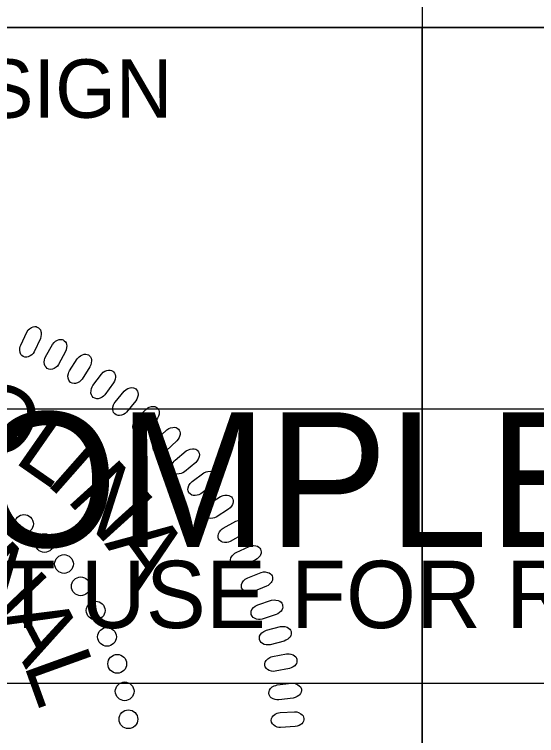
# Model space of a CAD drawing. Extents: x 505602 to 507286, y 483109 to 484209.
# Drawn here: x 507134.2 to 507178.9, y 484098.1 to 484159.8 of the extents above; entities that cross this region are included whole.
import ezdxf

# ---------------------------------------------------------------- set-up
doc = ezdxf.new("R2010")
doc.units = 0
for name, color, linetype in [('Sheet Layout Profile Border Port 2', 7, 'Continuous'), ('Sheet PE Seal Cell', 7, 'Continuous'), ('Sheet Profile CELL', 7, 'Continuous'), ('Sheet Sticker Incomplete CELL', 7, 'Continuous')]:
    doc.layers.add(name, color=color, linetype=linetype)

msp = doc.modelspace()

# ---------------------------------------------------------------- linework, layer by layer
at = {"layer": 'Sheet Layout Profile Border Port 2'}
msp.add_lwpolyline([(506769.08, 484183.712), (507169.08, 484183.712), (507169.08, 483683.712), (506769.08, 483683.712)], close=True, dxfattribs=at)
at = {"layer": 'Sheet PE Seal Cell'}
for points in [[(507134.756, 484131.474), (507135.278, 484132.584), (507135.405, 484132.766), (507135.512, 484132.87), (507135.686, 484132.976), (507135.821, 484133.034), (507135.956, 484133.058), (507136.068, 484133.05), (507136.178, 484133.02), (507136.27, 484132.954), (507136.366, 484132.876), (507136.435, 484132.778), (507136.487, 484132.642), (507136.508, 484132.545), (507136.505, 484132.381), (507136.482, 484132.193), (507136.435, 484132.039), (507135.906, 484130.899), (507135.814, 484130.755), (507135.713, 484130.648), (507135.564, 484130.542), (507135.403, 484130.463), (507135.281, 484130.432), (507135.114, 484130.445), (507134.97, 484130.491), (507134.852, 484130.591), (507134.779, 484130.68), (507134.706, 484130.825), (507134.67, 484131.029), (507134.686, 484131.22), (507134.714, 484131.35)], [(507136.88, 484130.459), (507137.471, 484131.534), (507137.609, 484131.707), (507137.722, 484131.805), (507137.902, 484131.899), (507138.04, 484131.949), (507138.177, 484131.964), (507138.288, 484131.949), (507138.396, 484131.912), (507138.485, 484131.841), (507138.575, 484131.757), (507138.638, 484131.654), (507138.682, 484131.516), (507138.695, 484131.418), (507138.683, 484131.254), (507138.648, 484131.068), (507138.591, 484130.917), (507137.992, 484129.813), (507137.89, 484129.675), (507137.784, 484129.574), (507137.629, 484129.478), (507137.462, 484129.409), (507137.339, 484129.386), (507137.173, 484129.41), (507137.032, 484129.464), (507136.92, 484129.571), (507136.852, 484129.666), (507136.789, 484129.814), (507136.766, 484130.02), (507136.794, 484130.21), (507136.83, 484130.338)], [(507138.938, 484129.274), (507139.595, 484130.309), (507139.744, 484130.475), (507139.863, 484130.564), (507140.049, 484130.647), (507140.19, 484130.688), (507140.327, 484130.695), (507140.437, 484130.673), (507140.543, 484130.629), (507140.626, 484130.553), (507140.711, 484130.463), (507140.768, 484130.357), (507140.802, 484130.216), (507140.81, 484130.117), (507140.787, 484129.954), (507140.741, 484129.771), (507140.674, 484129.624), (507140.007, 484128.559), (507139.897, 484128.428), (507139.784, 484128.335), (507139.623, 484128.248), (507139.454, 484128.19), (507139.329, 484128.174), (507139.164, 484128.208), (507139.027, 484128.272), (507138.923, 484128.385), (507138.861, 484128.484), (507138.807, 484128.636), (507138.797, 484128.843), (507138.837, 484129.031), (507138.881, 484129.156)], [(507140.938, 484128.001), (507141.659, 484128.993), (507141.818, 484129.149), (507141.943, 484129.231), (507142.133, 484129.302), (507142.276, 484129.333), (507142.413, 484129.332), (507142.522, 484129.302), (507142.625, 484129.253), (507142.703, 484129.171), (507142.782, 484129.077), (507142.832, 484128.967), (507142.858, 484128.824), (507142.86, 484128.724), (507142.826, 484128.564), (507142.769, 484128.384), (507142.693, 484128.241), (507141.96, 484127.221), (507141.842, 484127.097), (507141.723, 484127.01), (507141.558, 484126.934), (507141.384, 484126.886), (507141.259, 484126.879), (507141.097, 484126.923), (507140.964, 484126.995), (507140.866, 484127.115), (507140.811, 484127.217), (507140.767, 484127.372), (507140.77, 484127.58), (507140.821, 484127.765), (507140.873, 484127.887)], [(507142.832, 484126.584), (507143.614, 484127.529), (507143.783, 484127.674), (507143.912, 484127.749), (507144.107, 484127.808), (507144.251, 484127.831), (507144.389, 484127.82), (507144.495, 484127.785), (507144.594, 484127.728), (507144.668, 484127.642), (507144.741, 484127.542), (507144.783, 484127.429), (507144.8, 484127.286), (507144.796, 484127.186), (507144.751, 484127.028), (507144.683, 484126.852), (507144.599, 484126.714), (507143.804, 484125.742), (507143.678, 484125.625), (507143.554, 484125.546), (507143.384, 484125.481), (507143.208, 484125.444), (507143.082, 484125.445), (507142.923, 484125.499), (507142.795, 484125.579), (507142.705, 484125.705), (507142.657, 484125.81), (507142.623, 484125.968), (507142.639, 484126.174), (507142.701, 484126.356), (507142.761, 484126.475)], [(507144.603, 484125.07), (507145.444, 484125.964), (507145.621, 484126.099), (507145.755, 484126.165), (507145.953, 484126.212), (507146.099, 484126.225), (507146.235, 484126.206), (507146.339, 484126.164), (507146.434, 484126.101), (507146.502, 484126.01), (507146.569, 484125.906), (507146.604, 484125.791), (507146.612, 484125.647), (507146.601, 484125.547), (507146.547, 484125.392), (507146.468, 484125.221), (507146.376, 484125.089), (507145.52, 484124.168), (507145.388, 484124.06), (507145.259, 484123.989), (507145.085, 484123.935), (507144.908, 484123.909), (507144.782, 484123.918), (507144.626, 484123.982), (507144.504, 484124.069), (507144.423, 484124.201), (507144.381, 484124.309), (507144.356, 484124.468), (507144.385, 484124.674), (507144.459, 484124.851), (507144.526, 484124.966)], [(507146.348, 484123.377), (507147.243, 484124.216), (507147.428, 484124.339), (507147.566, 484124.397), (507147.766, 484124.431), (507147.912, 484124.435), (507148.047, 484124.408), (507148.148, 484124.359), (507148.24, 484124.291), (507148.302, 484124.195), (507148.362, 484124.088), (507148.39, 484123.971), (507148.389, 484123.826), (507148.371, 484123.728), (507148.308, 484123.576), (507148.219, 484123.41), (507148.117, 484123.284), (507147.206, 484122.419), (507147.067, 484122.319), (507146.935, 484122.256), (507146.757, 484122.213), (507146.578, 484122.199), (507146.453, 484122.215), (507146.302, 484122.289), (507146.185, 484122.384), (507146.112, 484122.52), (507146.077, 484122.631), (507146.063, 484122.792), (507146.105, 484122.995), (507146.19, 484123.167), (507146.264, 484123.277)], [(507147.96, 484121.631), (507148.905, 484122.412), (507149.099, 484122.523), (507149.24, 484122.572), (507149.441, 484122.594), (507149.588, 484122.588), (507149.721, 484122.553), (507149.818, 484122.498), (507149.906, 484122.424), (507149.961, 484122.325), (507150.014, 484122.213), (507150.035, 484122.095), (507150.025, 484121.95), (507150.001, 484121.853), (507149.929, 484121.706), (507149.829, 484121.546), (507149.72, 484121.427), (507148.756, 484120.621), (507148.611, 484120.53), (507148.475, 484120.475), (507148.295, 484120.443), (507148.116, 484120.44), (507147.992, 484120.464), (507147.846, 484120.547), (507147.736, 484120.65), (507147.671, 484120.79), (507147.643, 484120.903), (507147.639, 484121.064), (507147.693, 484121.264), (507147.789, 484121.431), (507147.87, 484121.536)], [(507149.42, 484119.808), (507150.413, 484120.529), (507150.612, 484120.627), (507150.756, 484120.667), (507150.96, 484120.676), (507151.105, 484120.662), (507151.235, 484120.618), (507151.329, 484120.557), (507151.412, 484120.478), (507151.461, 484120.375), (507151.507, 484120.261), (507151.52, 484120.141), (507151.501, 484119.998), (507151.472, 484119.902), (507151.39, 484119.76), (507151.28, 484119.606), (507151.164, 484119.494), (507150.152, 484118.75), (507150.001, 484118.669), (507149.861, 484118.623), (507149.68, 484118.602), (507149.501, 484118.611), (507149.379, 484118.642), (507149.239, 484118.734), (507149.135, 484118.843), (507149.079, 484118.988), (507149.058, 484119.102), (507149.064, 484119.263), (507149.131, 484119.459), (507149.237, 484119.62), (507149.324, 484119.72)], [(507150.821, 484117.862), (507151.857, 484118.519), (507152.062, 484118.605), (507152.208, 484118.636), (507152.411, 484118.632), (507152.556, 484118.609), (507152.683, 484118.557), (507152.773, 484118.49), (507152.85, 484118.406), (507152.893, 484118.3), (507152.932, 484118.183), (507152.938, 484118.063), (507152.909, 484117.921), (507152.874, 484117.828), (507152.783, 484117.69), (507152.664, 484117.544), (507152.542, 484117.44), (507151.485, 484116.76), (507151.329, 484116.689), (507151.187, 484116.652), (507151.004, 484116.642), (507150.826, 484116.662), (507150.707, 484116.701), (507150.572, 484116.802), (507150.476, 484116.917), (507150.429, 484117.065), (507150.415, 484117.18), (507150.431, 484117.341), (507150.51, 484117.533), (507150.626, 484117.686), (507150.72, 484117.78)], [(507152.082, 484115.812), (507153.157, 484116.403), (507153.367, 484116.475), (507153.515, 484116.498), (507153.717, 484116.481), (507153.86, 484116.448), (507153.984, 484116.388), (507154.07, 484116.315), (507154.141, 484116.227), (507154.178, 484116.119), (507154.209, 484116), (507154.207, 484115.88), (507154.17, 484115.74), (507154.129, 484115.649), (507154.03, 484115.518), (507153.901, 484115.379), (507153.773, 484115.283), (507152.675, 484114.671), (507152.515, 484114.609), (507152.371, 484114.581), (507152.188, 484114.583), (507152.012, 484114.614), (507151.895, 484114.661), (507151.767, 484114.769), (507151.678, 484114.891), (507151.641, 484115.041), (507151.634, 484115.157), (507151.66, 484115.317), (507151.751, 484115.503), (507151.876, 484115.648), (507151.976, 484115.737)], [(507153.189, 484113.729), (507154.299, 484114.251), (507154.514, 484114.311), (507154.662, 484114.323), (507154.864, 484114.293), (507155.004, 484114.252), (507155.124, 484114.185), (507155.205, 484114.107), (507155.271, 484114.014), (507155.3, 484113.904), (507155.324, 484113.783), (507155.315, 484113.663), (507155.269, 484113.526), (507155.222, 484113.438), (507155.115, 484113.313), (507154.978, 484113.183), (507154.843, 484113.095), (507153.709, 484112.553), (507153.546, 484112.502), (507153.4, 484112.482), (507153.219, 484112.496), (507153.044, 484112.538), (507152.93, 484112.591), (507152.809, 484112.709), (507152.728, 484112.835), (507152.7, 484112.987), (507152.701, 484113.104), (507152.737, 484113.261), (507152.84, 484113.441), (507152.974, 484113.579), (507153.079, 484113.66)], [(507154.169, 484111.568), (507155.31, 484112.019), (507155.527, 484112.065), (507155.676, 484112.068), (507155.875, 484112.026), (507156.013, 484111.976), (507156.128, 484111.901), (507156.204, 484111.818), (507156.264, 484111.721), (507156.286, 484111.61), (507156.302, 484111.488), (507156.286, 484111.369), (507156.231, 484111.234), (507156.179, 484111.149), (507156.065, 484111.032), (507155.92, 484110.91), (507155.78, 484110.831), (507154.614, 484110.361), (507154.448, 484110.32), (507154.301, 484110.31), (507154.12, 484110.335), (507153.949, 484110.388), (507153.839, 484110.449), (507153.725, 484110.573), (507153.652, 484110.705), (507153.634, 484110.858), (507153.642, 484110.974), (507153.688, 484111.129), (507153.802, 484111.302), (507153.944, 484111.431), (507154.054, 484111.506)], [(507155.042, 484109.254), (507156.21, 484109.633), (507156.43, 484109.665), (507156.579, 484109.658), (507156.775, 484109.604), (507156.909, 484109.546), (507157.02, 484109.463), (507157.09, 484109.376), (507157.143, 484109.275), (507157.159, 484109.163), (507157.168, 484109.04), (507157.143, 484108.922), (507157.08, 484108.791), (507157.023, 484108.71), (507156.901, 484108.599), (507156.749, 484108.487), (507156.604, 484108.416), (507155.411, 484108.021), (507155.243, 484107.991), (507155.097, 484107.991), (507154.918, 484108.026), (507154.75, 484108.09), (507154.644, 484108.158), (507154.538, 484108.288), (507154.473, 484108.425), (507154.465, 484108.579), (507154.48, 484108.694), (507154.536, 484108.846), (507154.66, 484109.012), (507154.81, 484109.132), (507154.924, 484109.2)], [(507155.788, 484107.081), (507156.976, 484107.385), (507157.197, 484107.403), (507157.346, 484107.388), (507157.538, 484107.321), (507157.669, 484107.255), (507157.773, 484107.166), (507157.838, 484107.074), (507157.885, 484106.97), (507157.894, 484106.857), (507157.894, 484106.733), (507157.863, 484106.618), (507157.792, 484106.491), (507157.73, 484106.413), (507157.601, 484106.311), (507157.442, 484106.208), (507157.293, 484106.147), (507156.078, 484105.828), (507155.908, 484105.808), (507155.762, 484105.817), (507155.585, 484105.864), (507155.422, 484105.937), (507155.32, 484106.012), (507155.224, 484106.149), (507155.167, 484106.289), (507155.169, 484106.444), (507155.191, 484106.557), (507155.256, 484106.705), (507155.39, 484106.863), (507155.548, 484106.973), (507155.666, 484107.034)], [(507156.297, 484104.827), (507157.502, 484105.056), (507157.725, 484105.06), (507157.872, 484105.035), (507158.059, 484104.957), (507158.185, 484104.882), (507158.285, 484104.786), (507158.343, 484104.691), (507158.384, 484104.585), (507158.385, 484104.471), (507158.378, 484104.347), (507158.339, 484104.234), (507158.261, 484104.113), (507158.194, 484104.039), (507158.059, 484103.944), (507157.894, 484103.852), (507157.742, 484103.8), (507156.508, 484103.558), (507156.337, 484103.548), (507156.192, 484103.566), (507156.019, 484103.625), (507155.861, 484103.709), (507155.764, 484103.789), (507155.675, 484103.932), (507155.628, 484104.076), (507155.639, 484104.229), (507155.669, 484104.342), (507155.743, 484104.485), (507155.887, 484104.634), (507156.052, 484104.735), (507156.173, 484104.787)], [(507156.695, 484102.387), (507157.913, 484102.54), (507158.135, 484102.531), (507158.28, 484102.497), (507158.462, 484102.407), (507158.584, 484102.324), (507158.677, 484102.223), (507158.729, 484102.124), (507158.763, 484102.015), (507158.757, 484101.902), (507158.742, 484101.779), (507158.696, 484101.667), (507158.61, 484101.551), (507158.539, 484101.482), (507158.398, 484101.397), (507158.228, 484101.314), (507158.072, 484101.272), (507156.826, 484101.108), (507156.655, 484101.109), (507156.511, 484101.136), (507156.342, 484101.205), (507156.189, 484101.299), (507156.098, 484101.386), (507156.018, 484101.533), (507155.981, 484101.68), (507156.002, 484101.833), (507156.038, 484101.943), (507156.121, 484102.081), (507156.274, 484102.221), (507156.444, 484102.31), (507156.569, 484102.356)], [(507156.939, 484100.023), (507158.163, 484100.099), (507158.384, 484100.075), (507158.527, 484100.032), (507158.704, 484099.931), (507158.819, 484099.841), (507158.905, 484099.733), (507158.951, 484099.632), (507158.979, 484099.521), (507158.966, 484099.408), (507158.944, 484099.287), (507158.89, 484099.179), (507158.797, 484099.068), (507158.721, 484099.003), (507158.576, 484098.926), (507158.401, 484098.855), (507158.243, 484098.823), (507156.989, 484098.737), (507156.819, 484098.749), (507156.676, 484098.786), (507156.512, 484098.865), (507156.366, 484098.968), (507156.28, 484099.06), (507156.21, 484099.213), (507156.181, 484099.361), (507156.211, 484099.512), (507156.255, 484099.62), (507156.346, 484099.753), (507156.508, 484099.883), (507156.683, 484099.962), (507156.81, 484099.999)]]:
    msp.add_lwpolyline(points, close=True, dxfattribs=at)
for centre in [(507135.036, 484116.168), (507136.787, 484114.534), (507138.459, 484112.741), (507139.891, 484110.828), (507141.165, 484108.756), (507142.137, 484106.507), (507143.012, 484104.196), (507143.648, 484101.845), (507143.966, 484099.455)]:
    msp.add_circle(centre, 0.801, dxfattribs=at)
at = {"layer": 'Sheet Profile CELL'}
msp.add_line((507169.08, 484158.662), (507169.08, 484046.212), dxfattribs=at)
for points in [[(507069.03, 484183.712), (507269.08, 484183.712), (507269.08, 484158.662), (507069.03, 484158.662)], [(507069.03, 484158.662), (507169.08, 484158.662), (507169.08, 484046.162), (507069.03, 484046.162)], [(507169.08, 484158.662), (507269.08, 484158.662), (507269.08, 484046.162), (507169.08, 484046.162)]]:
    msp.add_lwpolyline(points, close=True, dxfattribs=at)
at = {"layer": 'Sheet Sticker Incomplete CELL'}
msp.add_lwpolyline([(507095.597, 484102.505), (507095.597, 484126.005), (507242.597, 484126.005), (507242.597, 484102.505)], close=True, dxfattribs=at)

# ---------------------------------------------------------------- texts
at = {"layer": 'Sheet PE Seal Cell'}
for s, rotation, p in [('O', 331.63025, (507129.326, 484124.065)), ('L', 325.14089, (507134.059, 484121.534)), ('I', 318.65154, (507136.752, 484119.681)), ('N', 312.16218, (507138.557, 484118.261)), ('A', 305.67282, (507141.877, 484114.48)), ('N', 313.65025, (507129.525, 484111.222)), ('A', 297.77065, (507132.862, 484108.141)), ('L', 289.83086, (507134.985, 484104.147))]:
    msp.add_text(s, height=5.669, rotation=rotation, dxfattribs=at).set_placement(p)
at = {"layer": 'Sheet Profile CELL'}
msp.add_text('ROADWAY DESIGN', height=5.0001, dxfattribs=at).set_placement((507085.692, 484150.924))
at = {"layer": 'Sheet Sticker Incomplete CELL'}
for s, height, p in [('INCOMPLETE PLANS', 11.52, (507104.547, 484114.205)), ('DO NOT USE FOR R/W ACQUISITION', 5.76, (507107.797, 484107.255))]:
    msp.add_text(s, height=height, dxfattribs=at).set_placement(p)

doc.saveas('drawing.dxf')
